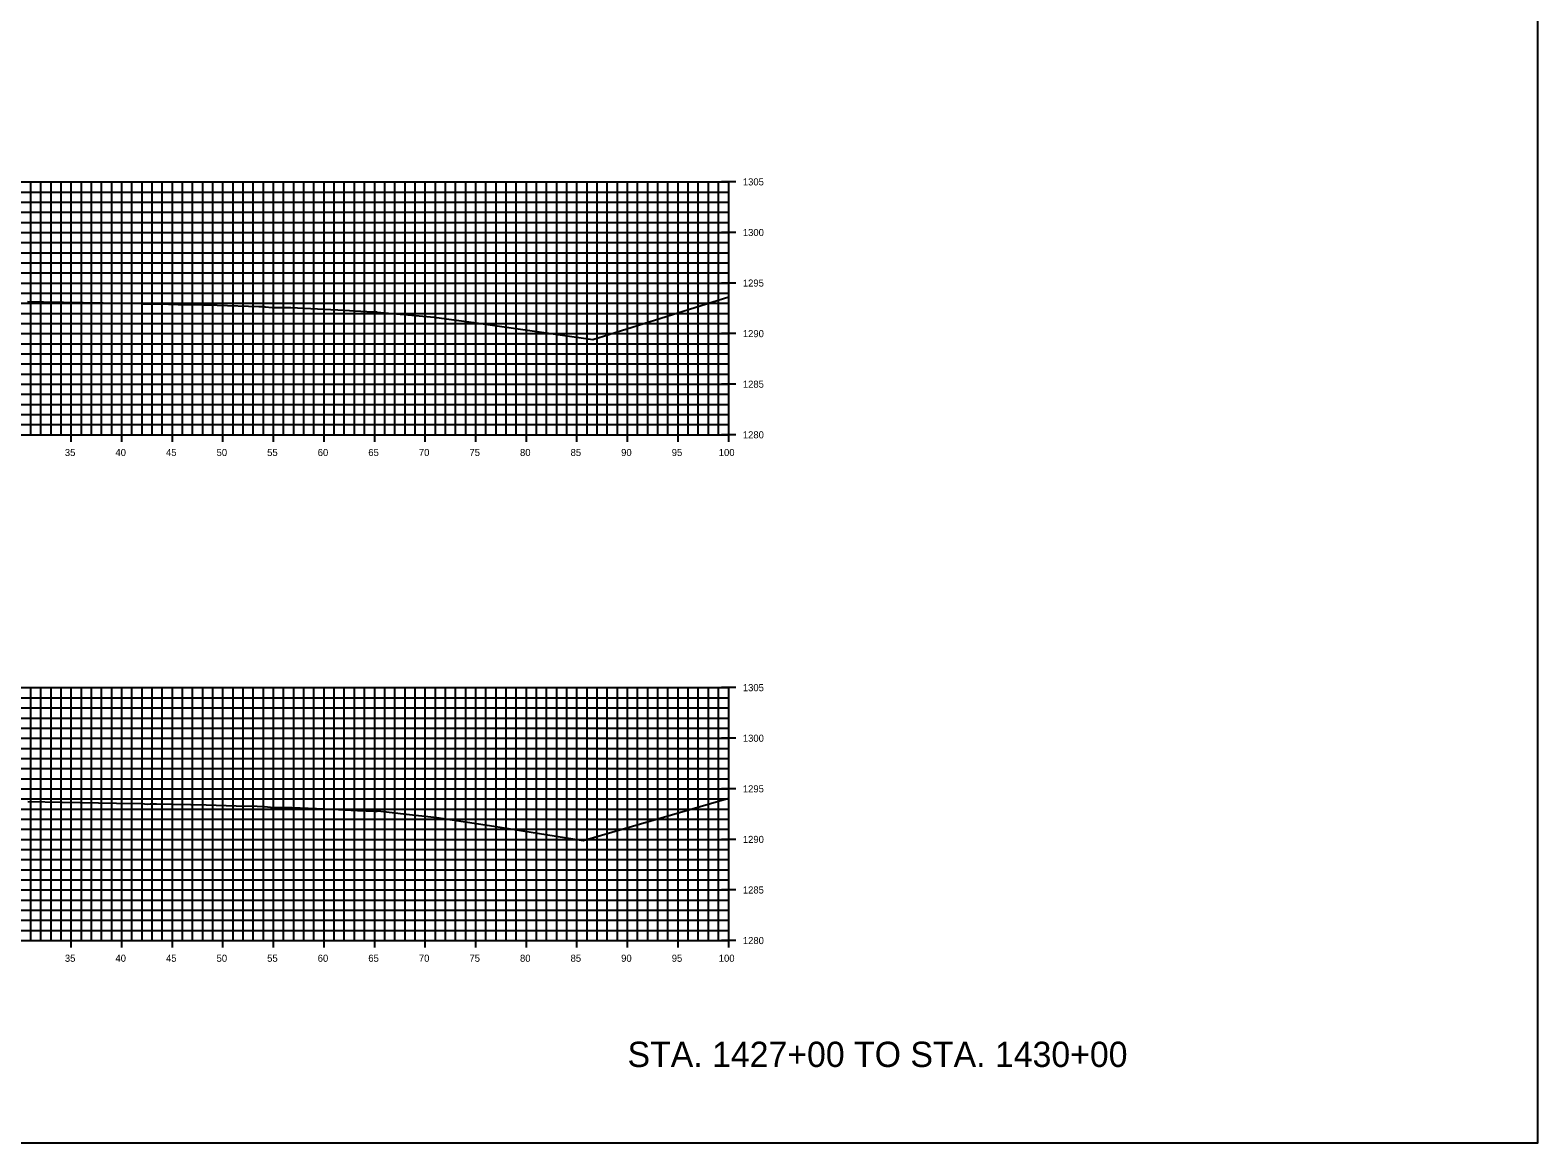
# Model space of a CAD drawing. Extents: x 674939 to 678919, y 750652 to 765176.
# Drawn here: x 678769.5 to 678918.5, y 758052.6 to 758162.6 of the extents above; entities that cross this region are included whole.
import ezdxf

# ---------------------------------------------------------------- set-up
doc = ezdxf.new("R2010")
doc.units = 0
for name, color, linetype in [('Level 10', 7, 'Continuous'), ('Level 20', 7, 'Continuous'), ('Level 21', 7, 'Continuous'), ('Level 4', 7, 'Continuous'), ('Level 8', 7, 'Continuous'), ('Level 9', 7, 'Continuous')]:
    doc.layers.add(name, color=color, linetype=linetype)

msp = doc.modelspace()

# ---------------------------------------------------------------- linework, layer by layer
at = {"layer": 'Level 10'}
for points in [[(678769.22, 758135.72), (678770.79, 758135.69), (678780.62, 758135.52), (678780.67, 758135.51), (678781.19, 758135.49), (678781.33, 758135.49), (678782.19, 758135.51), (678784.09, 758135.44), (678785.02, 758135.42), (678787.95, 758135.37), (678792.09, 758135.24), (678792.62, 758135.22), (678792.62, 758135.22), (678792.62, 758135.22), (678792.7, 758135.21), (678793.39, 758135.14), (678794.94, 758135.13), (678795.24, 758135.13), (678799.21, 758134.92), (678799.9, 758134.89), (678803.31, 758134.71), (678803.7, 758134.69), (678803.77, 758134.68), (678807.57, 758134.35), (678809.4, 758134.18), (678813.57, 758133.61), (678825.1, 758131.96), (678838.53, 758136.19)], [(678769.25, 758086.28), (678772.64, 758086.23), (678778.01, 758086.14), (678780.44, 758086.09), (678780.76, 758086.06), (678781.04, 758086.03), (678781.33, 758086.06), (678781.96, 758086.07), (678783.56, 758086.03), (678785.36, 758085.99), (678786.87, 758085.96), (678789.83, 758085.87), (678791.9, 758085.82), (678792.64, 758085.8), (678792.64, 758085.8), (678792.64, 758085.8), (678792.93, 758085.76), (678793.24, 758085.72), (678794.3, 758085.71), (678795.34, 758085.7), (678797.77, 758085.6), (678799.94, 758085.51), (678801.84, 758085.42), (678803.54, 758085.34), (678803.75, 758085.35), (678803.84, 758085.37), (678806.39, 758085.08), (678809.67, 758084.71), (678815.3, 758083.86), (678824.15, 758082.44), (678838.53, 758086.63)]]:
    msp.add_lwpolyline(points, dxfattribs=at)
at = {"layer": 'Level 20'}
for p, q in [((678638.53, 758147.55), (678838.53, 758147.55)), ((678769.53, 758122.55), (678769.53, 758147.55)), ((678770.53, 758122.55), (678770.53, 758147.55)), ((678771.53, 758122.55), (678771.53, 758147.55)), ((678772.53, 758122.55), (678772.53, 758147.55)), ((678773.53, 758122.55), (678773.53, 758147.55)), ((678774.53, 758122.55), (678774.53, 758147.55)), ((678775.53, 758122.55), (678775.53, 758147.55)), ((678776.53, 758122.55), (678776.53, 758147.55)), ((678777.53, 758122.55), (678777.53, 758147.55)), ((678778.53, 758122.55), (678778.53, 758147.55)), ((678779.53, 758122.55), (678779.53, 758147.55)), ((678780.53, 758122.55), (678780.53, 758147.55)), ((678781.53, 758122.55), (678781.53, 758147.55)), ((678782.53, 758122.55), (678782.53, 758147.55)), ((678783.53, 758122.55), (678783.53, 758147.55)), ((678784.53, 758122.55), (678784.53, 758147.55)), ((678785.53, 758122.55), (678785.53, 758147.55)), ((678786.53, 758122.55), (678786.53, 758147.55)), ((678787.53, 758122.55), (678787.53, 758147.55)), ((678788.53, 758122.55), (678788.53, 758147.55)), ((678789.53, 758122.55), (678789.53, 758147.55)), ((678790.53, 758122.55), (678790.53, 758147.55)), ((678791.53, 758122.55), (678791.53, 758147.55)), ((678792.53, 758122.55), (678792.53, 758147.55)), ((678793.53, 758122.55), (678793.53, 758147.55)), ((678794.53, 758122.55), (678794.53, 758147.55)), ((678795.53, 758122.55), (678795.53, 758147.55)), ((678796.53, 758122.55), (678796.53, 758147.55)), ((678797.53, 758122.55), (678797.53, 758147.55)), ((678798.53, 758122.55), (678798.53, 758147.55)), ((678799.53, 758122.55), (678799.53, 758147.55)), ((678800.53, 758122.55), (678800.53, 758147.55)), ((678801.53, 758122.55), (678801.53, 758147.55)), ((678802.53, 758122.55), (678802.53, 758147.55)), ((678803.53, 758122.55), (678803.53, 758147.55)), ((678804.53, 758122.55), (678804.53, 758147.55)), ((678805.53, 758122.55), (678805.53, 758147.55)), ((678806.53, 758122.55), (678806.53, 758147.55)), ((678807.53, 758122.55), (678807.53, 758147.55)), ((678808.53, 758122.55), (678808.53, 758147.55)), ((678809.53, 758122.55), (678809.53, 758147.55)), ((678810.53, 758122.55), (678810.53, 758147.55)), ((678811.53, 758122.55), (678811.53, 758147.55)), ((678812.53, 758122.55), (678812.53, 758147.55)), ((678813.53, 758122.55), (678813.53, 758147.55)), ((678814.53, 758122.55), (678814.53, 758147.55)), ((678815.53, 758122.55), (678815.53, 758147.55)), ((678816.53, 758122.55), (678816.53, 758147.55)), ((678817.53, 758122.55), (678817.53, 758147.55)), ((678818.53, 758122.55), (678818.53, 758147.55)), ((678819.53, 758122.55), (678819.53, 758147.55)), ((678820.53, 758122.55), (678820.53, 758147.55)), ((678821.53, 758122.55), (678821.53, 758147.55)), ((678822.53, 758122.55), (678822.53, 758147.55)), ((678823.53, 758122.55), (678823.53, 758147.55)), ((678824.53, 758122.55), (678824.53, 758147.55)), ((678825.53, 758122.55), (678825.53, 758147.55)), ((678826.53, 758122.55), (678826.53, 758147.55)), ((678827.53, 758122.55), (678827.53, 758147.55)), ((678828.53, 758122.55), (678828.53, 758147.55)), ((678829.53, 758122.55), (678829.53, 758147.55)), ((678830.53, 758122.55), (678830.53, 758147.55)), ((678831.53, 758122.55), (678831.53, 758147.55)), ((678832.53, 758122.55), (678832.53, 758147.55)), ((678833.53, 758122.55), (678833.53, 758147.55)), ((678834.53, 758122.55), (678834.53, 758147.55)), ((678835.53, 758122.55), (678835.53, 758147.55)), ((678836.53, 758122.55), (678836.53, 758147.55)), ((678837.53, 758122.55), (678837.53, 758147.55)), ((678838.53, 758122.55), (678838.53, 758147.55)), ((678638.53, 758146.55), (678838.53, 758146.55)), ((678638.53, 758145.55), (678838.53, 758145.55)), ((678638.53, 758144.55), (678838.53, 758144.55)), ((678638.53, 758143.55), (678838.53, 758143.55)), ((678638.53, 758142.55), (678838.53, 758142.55)), ((678638.53, 758141.55), (678838.53, 758141.55)), ((678638.53, 758140.55), (678838.53, 758140.55)), ((678638.53, 758139.55), (678838.53, 758139.55)), ((678638.53, 758138.55), (678838.53, 758138.55)), ((678638.53, 758137.55), (678838.53, 758137.55)), ((678638.53, 758136.55), (678838.53, 758136.55)), ((678638.53, 758135.55), (678838.53, 758135.55)), ((678638.53, 758134.55), (678838.53, 758134.55)), ((678638.53, 758133.55), (678838.53, 758133.55)), ((678638.53, 758132.55), (678838.53, 758132.55)), ((678638.53, 758131.55), (678838.53, 758131.55)), ((678638.53, 758130.55), (678838.53, 758130.55)), ((678638.53, 758129.55), (678838.53, 758129.55)), ((678638.53, 758128.55), (678838.53, 758128.55)), ((678638.53, 758127.55), (678838.53, 758127.55)), ((678638.53, 758126.55), (678838.53, 758126.55)), ((678638.53, 758125.55), (678838.53, 758125.55)), ((678638.53, 758124.55), (678838.53, 758124.55)), ((678638.53, 758123.55), (678838.53, 758123.55)), ((678638.53, 758122.55), (678838.53, 758122.55)), ((678638.53, 758097.55), (678838.53, 758097.55)), ((678638.53, 758096.55), (678838.53, 758096.55)), ((678769.53, 758072.55), (678769.53, 758097.55)), ((678770.53, 758072.55), (678770.53, 758097.55)), ((678771.53, 758072.55), (678771.53, 758097.55)), ((678772.53, 758072.55), (678772.53, 758097.55)), ((678773.53, 758072.55), (678773.53, 758097.55)), ((678774.53, 758072.55), (678774.53, 758097.55)), ((678775.53, 758072.55), (678775.53, 758097.55)), ((678776.53, 758072.55), (678776.53, 758097.55)), ((678777.53, 758072.55), (678777.53, 758097.55)), ((678778.53, 758072.55), (678778.53, 758097.55)), ((678779.53, 758072.55), (678779.53, 758097.55)), ((678780.53, 758072.55), (678780.53, 758097.55)), ((678781.53, 758072.55), (678781.53, 758097.55)), ((678782.53, 758072.55), (678782.53, 758097.55)), ((678783.53, 758072.55), (678783.53, 758097.55)), ((678784.53, 758072.55), (678784.53, 758097.55)), ((678785.53, 758072.55), (678785.53, 758097.55)), ((678786.53, 758072.55), (678786.53, 758097.55)), ((678787.53, 758072.55), (678787.53, 758097.55)), ((678788.53, 758072.55), (678788.53, 758097.55)), ((678789.53, 758072.55), (678789.53, 758097.55)), ((678790.53, 758072.55), (678790.53, 758097.55)), ((678791.53, 758072.55), (678791.53, 758097.55)), ((678792.53, 758072.55), (678792.53, 758097.55)), ((678793.53, 758072.55), (678793.53, 758097.55)), ((678794.53, 758072.55), (678794.53, 758097.55)), ((678795.53, 758072.55), (678795.53, 758097.55)), ((678796.53, 758072.55), (678796.53, 758097.55)), ((678797.53, 758072.55), (678797.53, 758097.55)), ((678798.53, 758072.55), (678798.53, 758097.55)), ((678799.53, 758072.55), (678799.53, 758097.55)), ((678800.53, 758072.55), (678800.53, 758097.55)), ((678801.53, 758072.55), (678801.53, 758097.55)), ((678802.53, 758072.55), (678802.53, 758097.55)), ((678803.53, 758072.55), (678803.53, 758097.55)), ((678804.53, 758072.55), (678804.53, 758097.55)), ((678805.53, 758072.55), (678805.53, 758097.55)), ((678806.53, 758072.55), (678806.53, 758097.55)), ((678807.53, 758072.55), (678807.53, 758097.55)), ((678808.53, 758072.55), (678808.53, 758097.55)), ((678809.53, 758072.55), (678809.53, 758097.55)), ((678810.53, 758072.55), (678810.53, 758097.55)), ((678811.53, 758072.55), (678811.53, 758097.55)), ((678812.53, 758072.55), (678812.53, 758097.55)), ((678813.53, 758072.55), (678813.53, 758097.55)), ((678814.53, 758072.55), (678814.53, 758097.55)), ((678815.53, 758072.55), (678815.53, 758097.55)), ((678816.53, 758072.55), (678816.53, 758097.55)), ((678817.53, 758072.55), (678817.53, 758097.55)), ((678818.53, 758072.55), (678818.53, 758097.55)), ((678819.53, 758072.55), (678819.53, 758097.55)), ((678820.53, 758072.55), (678820.53, 758097.55)), ((678821.53, 758072.55), (678821.53, 758097.55)), ((678822.53, 758072.55), (678822.53, 758097.55)), ((678823.53, 758072.55), (678823.53, 758097.55)), ((678824.53, 758072.55), (678824.53, 758097.55)), ((678825.53, 758072.55), (678825.53, 758097.55)), ((678826.53, 758072.55), (678826.53, 758097.55)), ((678827.53, 758072.55), (678827.53, 758097.55)), ((678828.53, 758072.55), (678828.53, 758097.55)), ((678829.53, 758072.55), (678829.53, 758097.55)), ((678830.53, 758072.55), (678830.53, 758097.55)), ((678831.53, 758072.55), (678831.53, 758097.55)), ((678832.53, 758072.55), (678832.53, 758097.55)), ((678833.53, 758072.55), (678833.53, 758097.55)), ((678834.53, 758072.55), (678834.53, 758097.55)), ((678835.53, 758072.55), (678835.53, 758097.55)), ((678836.53, 758072.55), (678836.53, 758097.55)), ((678837.53, 758072.55), (678837.53, 758097.55)), ((678838.53, 758072.55), (678838.53, 758097.55)), ((678638.53, 758095.55), (678838.53, 758095.55)), ((678638.53, 758094.55), (678838.53, 758094.55)), ((678638.53, 758093.55), (678838.53, 758093.55)), ((678638.53, 758092.55), (678838.53, 758092.55)), ((678638.53, 758091.55), (678838.53, 758091.55)), ((678638.53, 758090.55), (678838.53, 758090.55)), ((678638.53, 758089.55), (678838.53, 758089.55)), ((678638.53, 758088.55), (678838.53, 758088.55)), ((678638.53, 758087.55), (678838.53, 758087.55)), ((678638.53, 758086.55), (678838.53, 758086.55)), ((678638.53, 758085.55), (678838.53, 758085.55)), ((678638.53, 758084.55), (678838.53, 758084.55)), ((678638.53, 758083.55), (678838.53, 758083.55)), ((678638.53, 758082.55), (678838.53, 758082.55)), ((678638.53, 758081.55), (678838.53, 758081.55)), ((678638.53, 758080.55), (678838.53, 758080.55)), ((678638.53, 758079.55), (678838.53, 758079.55)), ((678638.53, 758078.55), (678838.53, 758078.55)), ((678638.53, 758077.55), (678838.53, 758077.55)), ((678638.53, 758076.55), (678838.53, 758076.55)), ((678638.53, 758075.55), (678838.53, 758075.55)), ((678638.53, 758074.55), (678838.53, 758074.55)), ((678638.53, 758073.55), (678838.53, 758073.55)), ((678638.53, 758072.55), (678838.53, 758072.55))]:
    msp.add_line(p, q, dxfattribs=at)
at = {"layer": 'Level 4'}
msp.add_lwpolyline([(678578.53, 758052.55), (678918.53, 758052.55), (678918.53, 758272.55), (678578.53, 758272.55)], close=True, dxfattribs=at)
at = {"layer": 'Level 8'}
for p, q in [((678839.23, 758147.55), (678837.83, 758147.55)), ((678838.53, 758122.55), (678838.53, 758147.55)), ((678839.23, 758142.55), (678837.83, 758142.55)), ((678839.23, 758137.55), (678837.83, 758137.55)), ((678839.23, 758132.55), (678837.83, 758132.55)), ((678839.23, 758127.55), (678837.83, 758127.55)), ((678773.53, 758121.85), (678773.53, 758123.25)), ((678778.53, 758121.85), (678778.53, 758123.25)), ((678783.53, 758121.85), (678783.53, 758123.25)), ((678788.53, 758121.85), (678788.53, 758123.25)), ((678793.53, 758121.85), (678793.53, 758123.25)), ((678798.53, 758121.85), (678798.53, 758123.25)), ((678803.53, 758121.85), (678803.53, 758123.25)), ((678808.53, 758121.85), (678808.53, 758123.25)), ((678813.53, 758121.85), (678813.53, 758123.25)), ((678818.53, 758121.85), (678818.53, 758123.25)), ((678823.53, 758121.85), (678823.53, 758123.25)), ((678828.53, 758121.85), (678828.53, 758123.25)), ((678833.53, 758121.85), (678833.53, 758123.25)), ((678838.53, 758121.85), (678838.53, 758123.25)), ((678638.53, 758122.55), (678838.53, 758122.55)), ((678839.23, 758122.55), (678837.83, 758122.55)), ((678839.23, 758097.55), (678837.83, 758097.55)), ((678838.53, 758072.55), (678838.53, 758097.55)), ((678839.23, 758092.55), (678837.83, 758092.55)), ((678839.23, 758087.55), (678837.83, 758087.55)), ((678839.23, 758082.55), (678837.83, 758082.55)), ((678839.23, 758077.55), (678837.83, 758077.55)), ((678638.53, 758072.55), (678838.53, 758072.55)), ((678773.53, 758071.85), (678773.53, 758073.25)), ((678778.53, 758071.85), (678778.53, 758073.25)), ((678783.53, 758071.85), (678783.53, 758073.25)), ((678788.53, 758071.85), (678788.53, 758073.25)), ((678793.53, 758071.85), (678793.53, 758073.25)), ((678798.53, 758071.85), (678798.53, 758073.25)), ((678803.53, 758071.85), (678803.53, 758073.25)), ((678808.53, 758071.85), (678808.53, 758073.25)), ((678813.53, 758071.85), (678813.53, 758073.25)), ((678818.53, 758071.85), (678818.53, 758073.25)), ((678823.53, 758071.85), (678823.53, 758073.25)), ((678828.53, 758071.85), (678828.53, 758073.25)), ((678833.53, 758071.85), (678833.53, 758073.25)), ((678839.23, 758072.55), (678837.83, 758072.55)), ((678838.53, 758071.85), (678838.53, 758073.25))]:
    msp.add_line(p, q, dxfattribs=at)

# ---------------------------------------------------------------- texts
at = {"layer": 'Level 21'}
msp.add_text('STA. 1427+00 TO STA. 1430+00', height=2.5, dxfattribs=at).set_placement((678828.53, 758060.05))
at = {"layer": 'Level 9'}
for s, p in [('1305', (678839.93, 758147.2)), ('1300', (678839.93, 758142.2)), ('1295', (678839.93, 758137.2)), ('1290', (678839.93, 758132.2)), ('1285', (678839.93, 758127.2)), ('1280', (678839.93, 758122.2)), ('35', (678772.9, 758120.45)), ('40', (678777.9, 758120.45)), ('45', (678782.9, 758120.45)), ('50', (678787.9, 758120.45)), ('55', (678792.9, 758120.45)), ('60', (678797.9, 758120.45)), ('65', (678802.9, 758120.45)), ('70', (678807.9, 758120.45)), ('75', (678812.9, 758120.45)), ('80', (678817.9, 758120.45)), ('85', (678822.9, 758120.45)), ('90', (678827.9, 758120.45)), ('95', (678832.9, 758120.45)), ('100', (678837.55, 758120.45)), ('1305', (678839.93, 758097.2)), ('1300', (678839.93, 758092.2)), ('1295', (678839.93, 758087.2)), ('1290', (678839.93, 758082.2)), ('1285', (678839.93, 758077.2)), ('1280', (678839.93, 758072.2)), ('35', (678772.9, 758070.45)), ('40', (678777.9, 758070.45)), ('45', (678782.9, 758070.45)), ('50', (678787.9, 758070.45)), ('55', (678792.9, 758070.45)), ('60', (678797.9, 758070.45)), ('65', (678802.9, 758070.45)), ('70', (678807.9, 758070.45)), ('75', (678812.9, 758070.45)), ('80', (678817.9, 758070.45)), ('85', (678822.9, 758070.45)), ('90', (678827.9, 758070.45)), ('95', (678832.9, 758070.45)), ('100', (678837.55, 758070.45))]:
    msp.add_text(s, height=0.7, dxfattribs=at).set_placement(p)

doc.saveas('drawing.dxf')
